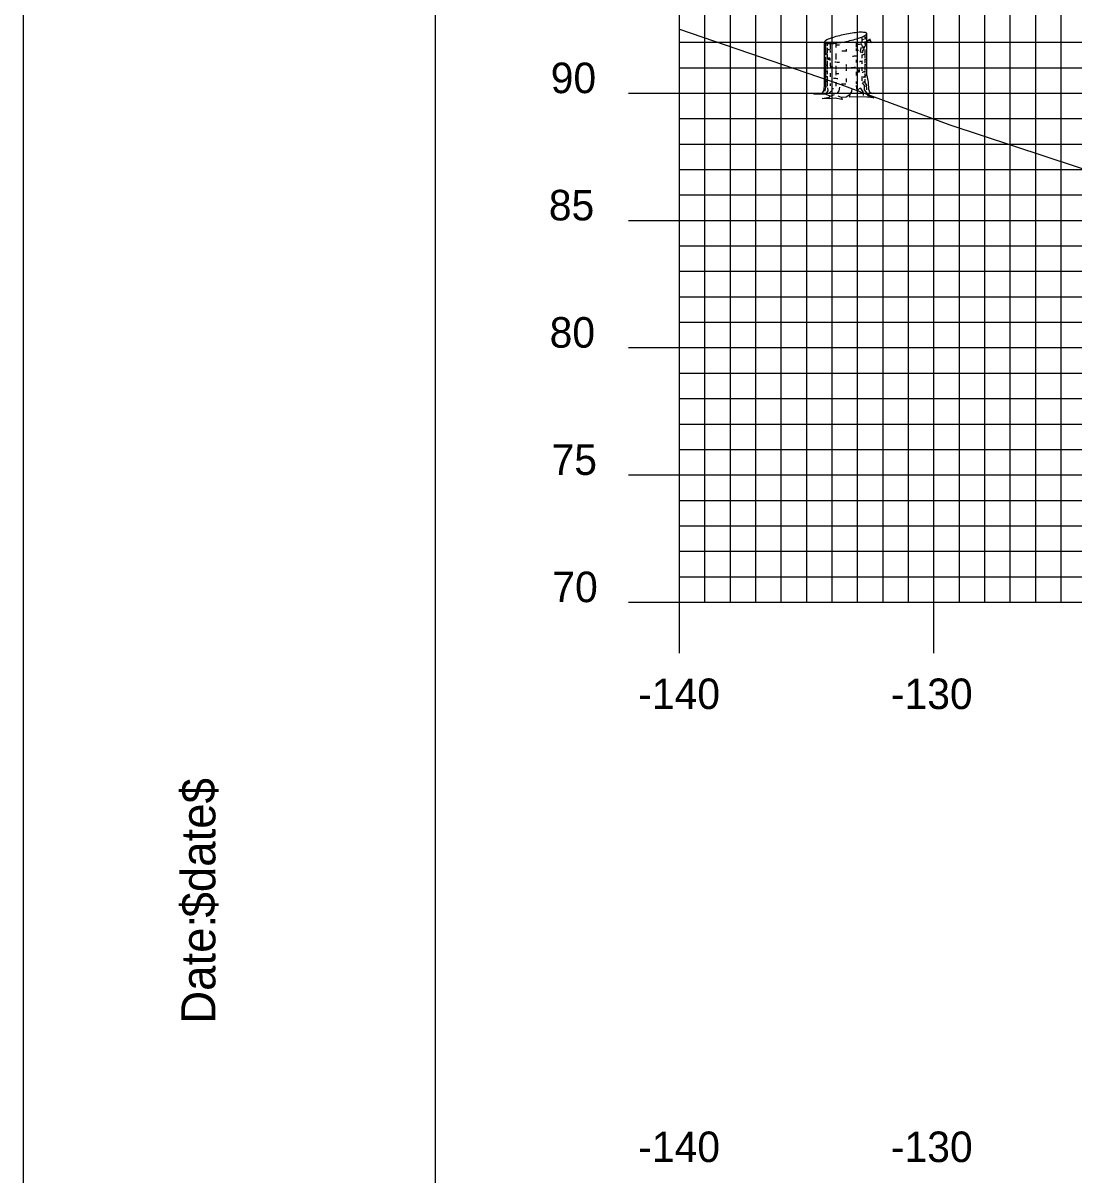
# Model space of a CAD drawing. Extents: x 857504 to 857847, y 364765 to 364985.
# Drawn here: x 857503.52 to 857544.81, y 364895.8 to 364941.06 of the extents above; entities that cross this region are included whole.
import ezdxf

# ---------------------------------------------------------------- set-up
doc = ezdxf.new("R2010")
doc.units = 0
for name, color, linetype in [('BORDER', 7, 'Continuous'), ('H_V ANNOTATION', 7, 'Continuous'), ('M_Trees_Conifer_Pay', 7, 'Continuous'), ('MAJOR', 7, 'Continuous'), ('MINOR', 7, 'Continuous'), ('PLOT BOUNDARY', 7, 'Continuous'), ('S_Roadway_Centerline', 7, 'Continuous')]:
    doc.layers.add(name, color=color, linetype=linetype)

msp = doc.modelspace()

# ---------------------------------------------------------------- linework, layer by layer
at = {"layer": 'BORDER'}
msp.add_lwpolyline([(857519.708, 364771.302), (857839.708, 364771.302), (857839.708, 364981.302), (857519.708, 364981.302)], close=True, dxfattribs=at)
at = {"layer": 'M_Trees_Conifer_Pay'}
for p, q in [((857535.003, 364938.582), (857535.003, 364940.304)), ((857535.05, 364940.266), (857535.05, 364939.795)), ((857535.108, 364940.255), (857535.108, 364940.158)), ((857535.234, 364940.247), (857535.234, 364940.015)), ((857535.453, 364940.268), (857535.453, 364940.1)), ((857536.249, 364940.31), (857536.249, 364940.11)), ((857536.478, 364940.506), (857536.478, 364940.283)), ((857536.595, 364940.567), (857536.595, 364940.404)), ((857536.595, 364940.337), (857536.595, 364940.209)), ((857536.667, 364938.992), (857536.667, 364940.639)), ((857535.108, 364940.083), (857535.108, 364939.879)), ((857535.108, 364939.822), (857535.108, 364939.622)), ((857535.234, 364939.974), (857535.234, 364939.9)), ((857535.453, 364939.863), (857535.453, 364939.626)), ((857535.859, 364940.036), (857535.859, 364939.941)), ((857536.249, 364940.053), (857536.249, 364939.964)), ((857536.478, 364940.194), (857536.478, 364940.147)), ((857536.478, 364939.812), (857536.478, 364939.68)), ((857536.535, 364940.011), (857536.484, 364939.952)), ((857536.595, 364940.022), (857536.595, 364939.686)), ((857535.05, 364939.731), (857535.05, 364939.423)), ((857535.05, 364939.375), (857535.05, 364938.883)), ((857535.108, 364939.575), (857535.108, 364939.239)), ((857535.234, 364939.497), (857535.234, 364939.358)), ((857535.453, 364939.381), (857535.453, 364939.229)), ((857535.859, 364939.423), (857535.859, 364939.348)), ((857535.859, 364939.324), (857535.859, 364939.175)), ((857536.249, 364939.616), (857536.249, 364939.511)), ((857536.478, 364939.569), (857536.478, 364939.459)), ((857536.478, 364939.324), (857536.478, 364939.182)), ((857536.595, 364939.649), (857536.595, 364939.486)), ((857536.595, 364939.439), (857536.595, 364939.223)), ((857535.108, 364939.186), (857535.108, 364939.05)), ((857535.108, 364938.951), (857535.108, 364938.572)), ((857535.234, 364939.087), (857535.234, 364938.945)), ((857535.453, 364939.186), (857535.453, 364939.013)), ((857535.859, 364938.883), (857535.859, 364938.73)), ((857536.249, 364939.144), (857536.249, 364938.998)), ((857536.478, 364938.955), (857536.478, 364938.782)), ((857536.595, 364939.192), (857536.595, 364939.118)), ((857536.595, 364939.077), (857536.595, 364938.904)), ((857535.05, 364938.829), (857535.05, 364938.582)), ((857535.234, 364938.683), (857535.234, 364938.589)), ((857535.453, 364938.735), (857535.453, 364938.582)), ((857536.249, 364938.766), (857536.249, 364938.677)), ((857535.234, 364938.189), (857535.396, 364938.253)), ((857535.671, 364938.125), (857535.545, 364938.189))]:
    msp.add_line(p, q, dxfattribs=at)
for points in [[(857536.484, 364940.137), (857536.52, 364940.063), (857536.567, 364940.12), (857536.625, 364940.188), (857536.718, 364940.382), (857536.782, 364940.429), (857536.813, 364940.436)], [(857536.498, 364939.884), (857536.535, 364940.011), (857536.598, 364940.127), (857536.629, 364940.194), (857536.698, 364940.341)], [(857536.713, 364940.37), (857536.788, 364940.378), (857536.86, 364940.279)], [(857536.45, 364940.1), (857536.419, 364940.015), (857536.415, 364939.948), (857536.446, 364939.884)], [(857535.182, 364939.61), (857535.176, 364939.705), (857535.219, 364939.682), (857535.219, 364939.587)], [(857536.321, 364939.211), (857536.333, 364939.134), (857536.38, 364939.144), (857536.368, 364939.311)], [(857536.667, 364938.992), (857536.718, 364938.73), (857536.734, 364938.457), (857536.792, 364938.331), (857536.928, 364938.301), (857536.697, 364938.263), (857536.697, 364938.263), (857536.703, 364938.216), (857536.951, 364938.121), (857536.676, 364938.138), (857536.321, 364938.158), (857535.999, 364938.148), (857536.006, 364938.23), (857535.858, 364938.148), (857535.671, 364938.125), (857535.695, 364938.057), (857535.427, 364938.1), (857535.207, 364938.074), (857534.914, 364938.091), (857535.203, 364938.148), (857535.234, 364938.189), (857535.071, 364938.247), (857534.834, 364938.257), (857534.593, 364938.257), (857534.935, 364938.315), (857534.976, 364938.395), (857535.003, 364938.582)], [(857536.592, 364938.85), (857536.598, 364938.704), (857536.646, 364938.636), (857536.656, 364938.436)], [(857535.05, 364938.535), (857535.029, 364938.457), (857535.009, 364938.362)], [(857535.129, 364938.515), (857535.134, 364938.399), (857535.081, 364938.31), (857535.071, 364938.247)], [(857535.291, 364938.541), (857535.291, 364938.41), (857535.203, 364938.31)], [(857535.518, 364938.301), (857535.585, 364938.395), (857535.612, 364938.535)], [(857536.006, 364938.23), (857536.08, 364938.372), (857536.09, 364938.473)], [(857536.256, 364938.599), (857536.267, 364938.473), (857536.341, 364938.43)], [(857536.535, 364938.21), (857536.52, 364938.348), (857536.446, 364938.477)], [(857536.493, 364938.704), (857536.567, 364938.599), (857536.572, 364938.426), (857536.697, 364938.263)]]:
    msp.add_lwpolyline(points, dxfattribs=at)
for centre, radius, start, end in [((857536.858, 364935.536), 5.179, 95.3794, 101.7194), ((857536.448, 364939.894), 0.802, 79.2194, 95.3794), ((857536.551, 364940.436), 0.251, 71.0501, 79.2194), ((857536.606, 364940.595), 0.0817, 56.7194, 71.0501), ((857536.622, 364940.619), 0.0527, 46.923, 56.7194), ((857536.636, 364940.635), 0.0314, 34.2194, 46.923), ((857535.034, 364940.303), 0.0314, 156.5158, 169.2194), ((857535.029, 364940.304), 0.0264, 169.2194, 180.0315), ((857535.025, 364940.304), 0.0226, 180.0315, 191.7194), ((857535.025, 364940.304), 0.0226, 191.7194, 203.4074), ((857535.054, 364940.294), 0.0527, 146.7194, 156.5158), ((857535.029, 364940.305), 0.0264, 203.4074, 214.2194), ((857535.033, 364940.308), 0.0314, 214.2194, 226.923), ((857535.078, 364940.278), 0.0817, 132.3887, 146.7194), ((857535.047, 364940.323), 0.0527, 226.923, 236.7194), ((857535.063, 364940.348), 0.0817, 236.7194, 251.0501), ((857535.192, 364940.154), 0.251, 124.2194, 132.3887), ((857535.118, 364940.507), 0.251, 251.0501, 259.2194), ((857535.501, 364939.698), 0.802, 108.0594, 124.2194), ((857535.221, 364941.049), 0.802, 259.2194, 275.3794), ((857536.858, 364935.536), 5.179, 101.7194, 108.0594), ((857534.811, 364945.407), 5.179, 275.3794, 281.7194), ((857535.835, 364944.316), 4.124, 264.6955, 266.7331), ((857534.811, 364945.407), 5.179, 281.7194, 288.0594), ((857535.835, 364944.316), 4.124, 276.238, 278.1032), ((857536.168, 364941.245), 0.802, 288.0594, 304.2194), ((857536.336, 364940.798), 0.571, 278.1032, 284.3667), ((857536.336, 364940.953), 0.571, 284.4317, 292.4132), ((857536.336, 364940.798), 0.571, 297.0237, 300), ((857536.478, 364940.789), 0.251, 304.2194, 312.3887), ((857536.535, 364940.608), 0.172, 300, 311.2506), ((857536.535, 364940.453), 0.172, 300, 311.2506), ((857536.592, 364940.665), 0.0817, 312.3887, 326.7194), ((857536.607, 364940.525), 0.0624, 311.2506, 330), ((857536.607, 364940.371), 0.0624, 311.2506, 330), ((857536.616, 364940.649), 0.0527, 326.7194, 336.5158), ((857536.623, 364940.516), 0.0441, 330, 343.9485), ((857536.623, 364940.361), 0.0441, 330, 343.9485), ((857536.641, 364940.638), 0.0264, 23.4074, 34.2194), ((857536.635, 364940.64), 0.0314, 336.5158, 349.2194), ((857536.644, 364940.639), 0.0226, 11.7194, 23.4074), ((857536.644, 364940.639), 0.0226, 0.0315, 11.7194), ((857536.64, 364940.639), 0.0264, 349.2194, 0.0315), ((857536.633, 364940.513), 0.0334, 343.9485, 354.2151), ((857536.633, 364940.359), 0.0334, 343.9485, 354.2151), ((857535.035, 364940.126), 0.0334, 163.9485, 180), ((857535.035, 364940.126), 0.0334, 180, 196.0515), ((857535.045, 364940.129), 0.0441, 196.0515, 210), ((857535.061, 364940.138), 0.0624, 210, 228.7494), ((857535.133, 364940.22), 0.172, 228.7494, 240), ((857535.333, 364940.565), 0.571, 240, 240.3367), ((857535.334, 364940.354), 0.571, 240, 247.0587), ((857535.333, 364940.565), 0.571, 246.8597, 257.9846), ((857535.833, 364944.083), 4.124, 268.0751, 270), ((857535.833, 364944.083), 4.124, 270, 270.3581), ((857535.835, 364943.872), 4.124, 273.7052, 275.9504), ((857535.833, 364944.083), 4.124, 275.7849, 277.0558), ((857536.335, 364940.354), 0.571, 284.4493, 297.0429), ((857536.633, 364939.915), 0.0334, 343.9485, 354.2151), ((857535.035, 364939.679), 0.0334, 163.9485, 180), ((857535.035, 364939.679), 0.0334, 180, 196.0515), ((857535.035, 364939.469), 0.0334, 163.9485, 180), ((857535.035, 364939.469), 0.0334, 180, 196.0515), ((857535.045, 364939.682), 0.0441, 196.0515, 210), ((857535.045, 364939.472), 0.0441, 196.0515, 210), ((857535.061, 364939.691), 0.0624, 210, 228.7494), ((857535.061, 364939.481), 0.0624, 210, 228.7494), ((857535.133, 364939.774), 0.172, 228.7494, 240), ((857535.133, 364939.564), 0.172, 228.7494, 240), ((857535.333, 364940.119), 0.571, 240, 240.3367), ((857535.333, 364939.909), 0.571, 240, 246.8597), ((857535.333, 364939.909), 0.571, 259.2707, 261.8968), ((857535.833, 364943.426), 4.124, 261.8968, 263.1474), ((857535.833, 364943.636), 4.124, 264.081, 266.6676), ((857535.833, 364943.426), 4.124, 270, 270.3581), ((857535.833, 364943.426), 4.124, 273.1493, 275.4569), ((857535.833, 364943.636), 4.124, 277.6125, 278.1032), ((857536.334, 364940.119), 0.571, 278.1032, 286.9296), ((857536.334, 364940.119), 0.571, 297.1896, 300), ((857536.334, 364939.909), 0.571, 297.1896, 300), ((857536.533, 364939.774), 0.172, 300, 311.2506), ((857536.533, 364939.564), 0.172, 300, 311.2506), ((857536.606, 364939.691), 0.0624, 311.2506, 330), ((857536.606, 364939.481), 0.0624, 311.2506, 330), ((857536.622, 364939.682), 0.0441, 330, 343.9485), ((857536.622, 364939.472), 0.0441, 330, 343.9485), ((857536.632, 364939.679), 0.0334, 343.9485, 354.2151), ((857536.632, 364939.469), 0.0334, 343.9485, 354.2151), ((857535.035, 364939.232), 0.0334, 163.9485, 180), ((857535.035, 364939.232), 0.0334, 180, 196.0515), ((857535.035, 364939.034), 0.0334, 163.9485, 180), ((857535.035, 364938.839), 0.0334, 163.9485, 180), ((857535.045, 364939.235), 0.0441, 196.0515, 210), ((857535.061, 364939.244), 0.0624, 210, 228.7494), ((857535.133, 364939.327), 0.172, 228.7494, 240), ((857535.333, 364939.672), 0.571, 240, 246.8597), ((857535.322, 364939.48), 0.571, 241.2369, 248.0268), ((857535.833, 364942.992), 4.124, 263.4991, 265.8397), ((857535.833, 364943.189), 4.124, 264.716, 266.3193), ((857536.334, 364939.672), 0.571, 285.3983, 297.1896), ((857536.334, 364939.474), 0.571, 289.2907, 300), ((857536.533, 364939.129), 0.172, 300, 311.2506), ((857536.606, 364939.046), 0.0624, 311.2506, 330), ((857536.622, 364939.037), 0.0441, 330, 343.9485), ((857536.632, 364939.034), 0.0334, 343.9485, 354.2151), ((857535.035, 364938.839), 0.0334, 180, 196.0515), ((857535.035, 364938.618), 0.0334, 163.9485, 180), ((857535.035, 364938.618), 0.0334, 180, 196.0515), ((857535.045, 364938.842), 0.0441, 196.0515, 210), ((857535.045, 364938.621), 0.0441, 196.0515, 210), ((857535.061, 364938.851), 0.0624, 210, 228.7494), ((857535.061, 364938.631), 0.0624, 210, 228.7494), ((857535.133, 364938.933), 0.172, 228.7494, 240), ((857535.133, 364938.713), 0.172, 228.7494, 240), ((857535.333, 364939.279), 0.571, 240, 246.8597), ((857535.333, 364939.058), 0.571, 240, 244.5314), ((857535.833, 364942.576), 4.124, 262.4438, 263.512), ((857535.833, 364942.796), 4.124, 267.8117, 270), ((857535.833, 364942.796), 4.124, 270, 270.1328), ((857535.833, 364942.796), 4.124, 275.7849, 276.7896), ((857535.833, 364942.576), 4.124, 277.3684, 278.1032), ((857536.334, 364939.058), 0.571, 278.1032, 281.637), ((857536.334, 364939.279), 0.571, 288.5067, 297.2721), ((857536.533, 364938.713), 0.172, 300, 311.2506), ((857536.606, 364938.631), 0.0624, 311.2506, 330), ((857536.622, 364938.621), 0.0441, 330, 343.9485), ((857536.632, 364938.618), 0.0334, 343.9485, 354.2151)]:
    msp.add_arc(centre, radius, start, end, dxfattribs=at)
at = {"layer": 'MAJOR'}
for p, q in [((857529.308, 364918.302), (857529.308, 364963.302)), ((857529.308, 364918.302), (857529.308, 364963.302)), ((857539.308, 364918.302), (857539.308, 364963.302)), ((857527.304, 364938.302), (857529.308, 364938.302)), ((857529.308, 364938.302), (857809.308, 364938.302)), ((857527.304, 364933.302), (857529.308, 364933.302)), ((857529.308, 364933.302), (857809.308, 364933.302)), ((857527.304, 364928.302), (857529.308, 364928.302)), ((857529.308, 364928.302), (857809.308, 364928.302)), ((857527.304, 364923.302), (857529.308, 364923.302)), ((857529.308, 364923.302), (857809.308, 364923.302)), ((857527.304, 364918.302), (857529.308, 364918.302)), ((857529.308, 364918.302), (857809.308, 364918.302)), ((857529.308, 364918.302), (857809.308, 364918.302)), ((857529.308, 364916.298), (857529.308, 364918.302)), ((857539.308, 364916.298), (857539.308, 364918.302))]:
    msp.add_line(p, q, dxfattribs=at)
at = {"layer": 'MINOR'}
for p, q in [((857530.308, 364918.302), (857530.308, 364963.302)), ((857531.308, 364918.302), (857531.308, 364963.302)), ((857532.308, 364918.302), (857532.308, 364963.302)), ((857533.308, 364918.302), (857533.308, 364963.302)), ((857534.308, 364918.302), (857534.308, 364963.302)), ((857535.308, 364918.302), (857535.308, 364963.302)), ((857536.308, 364918.302), (857536.308, 364963.302)), ((857537.308, 364918.302), (857537.308, 364963.302)), ((857538.308, 364918.302), (857538.308, 364963.302)), ((857540.308, 364918.302), (857540.308, 364963.302)), ((857541.308, 364918.302), (857541.308, 364963.302)), ((857542.308, 364918.302), (857542.308, 364963.302)), ((857543.308, 364918.302), (857543.308, 364963.302)), ((857544.308, 364918.302), (857544.308, 364963.302)), ((857529.308, 364940.302), (857809.308, 364940.302)), ((857529.308, 364940.302), (857531.312, 364940.302)), ((857529.308, 364939.302), (857809.308, 364939.302)), ((857529.308, 364939.302), (857531.312, 364939.302)), ((857529.308, 364937.302), (857809.308, 364937.302)), ((857529.308, 364937.302), (857531.312, 364937.302)), ((857529.308, 364936.302), (857809.308, 364936.302)), ((857529.308, 364936.302), (857531.312, 364936.302)), ((857529.308, 364935.302), (857809.308, 364935.302)), ((857529.308, 364935.302), (857531.312, 364935.302)), ((857529.308, 364934.302), (857809.308, 364934.302)), ((857529.308, 364934.302), (857531.312, 364934.302)), ((857529.308, 364932.302), (857809.308, 364932.302)), ((857529.308, 364932.302), (857531.312, 364932.302)), ((857529.308, 364931.302), (857809.308, 364931.302)), ((857529.308, 364931.302), (857531.312, 364931.302)), ((857529.308, 364930.302), (857809.308, 364930.302)), ((857529.308, 364930.302), (857531.312, 364930.302)), ((857529.308, 364929.302), (857809.308, 364929.302)), ((857529.308, 364929.302), (857531.312, 364929.302)), ((857529.308, 364927.302), (857809.308, 364927.302)), ((857529.308, 364927.302), (857531.312, 364927.302)), ((857529.308, 364926.302), (857809.308, 364926.302)), ((857529.308, 364926.302), (857531.312, 364926.302)), ((857529.308, 364925.302), (857809.308, 364925.302)), ((857529.308, 364925.302), (857531.312, 364925.302)), ((857529.308, 364924.302), (857809.308, 364924.302)), ((857529.308, 364924.302), (857531.312, 364924.302)), ((857529.308, 364922.302), (857809.308, 364922.302)), ((857529.308, 364922.302), (857531.312, 364922.302)), ((857529.308, 364921.302), (857809.308, 364921.302)), ((857529.308, 364921.302), (857531.312, 364921.302)), ((857529.308, 364920.302), (857809.308, 364920.302)), ((857529.308, 364920.302), (857531.312, 364920.302)), ((857529.308, 364919.302), (857809.308, 364919.302)), ((857529.308, 364919.302), (857531.312, 364919.302))]:
    msp.add_line(p, q, dxfattribs=at)
at = {"layer": 'PLOT BOUNDARY'}
msp.add_lwpolyline([(857503.521, 364765.184), (857843.521, 364765.184), (857843.521, 364985.184), (857503.521, 364985.184)], close=True, dxfattribs=at)
at = {"layer": 'S_Roadway_Centerline'}
msp.add_lwpolyline([(857529.308, 364940.811), (857535.655, 364938.647), (857539.931, 364937.059), (857552.4, 364932.939), (857565.242, 364930.376), (857566.855, 364930.129), (857567.294, 364930.134), (857584.882, 364929.536), (857589.507, 364929.07)], dxfattribs=at)

# ---------------------------------------------------------------- texts
at = {"layer": 'BORDER'}
for s, p in [('$date$', (857511.077, 364905.912)), ('Date:', (857511.077, 364901.736))]:
    msp.add_text(s, height=1.3392, rotation=90, dxfattribs=at).set_placement(p)
at = {"layer": 'H_V ANNOTATION'}
for s, p in [('90', (857524.252, 364938.302)), ('85', (857524.177, 364933.302)), ('80', (857524.209, 364928.302)), ('75', (857524.284, 364923.302)), ('70', (857524.316, 364918.302)), ('-140', (857527.692, 364914.102)), ('-130', (857537.617, 364914.102)), ('-140', (857527.692, 364896.302)), ('-130', (857537.617, 364896.302))]:
    msp.add_text(s, height=1.2, dxfattribs=at).set_placement(p)
at = {"layer": 'MAJOR'}
msp.add_text('-', height=0.012, dxfattribs=at).set_placement((857529.299, 364918.302))

doc.saveas('drawing.dxf')
